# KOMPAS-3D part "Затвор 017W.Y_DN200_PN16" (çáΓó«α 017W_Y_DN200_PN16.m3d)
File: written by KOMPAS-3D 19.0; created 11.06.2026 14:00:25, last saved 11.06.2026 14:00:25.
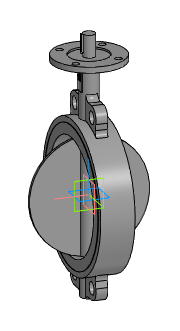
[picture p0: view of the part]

Document properties: Автор: Евгений; Полное имя файла: Z:\3.Личные\kachalov\001_3d для проектировщиков\x.x Тип 017W.Y(S) Затвор дисковый поворотный межфланцевый\_stp_Затвор 017W.Y_DN50-DN350\Затвор 017W_Y_DN200_PN16.m3d

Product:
- Part/product: Затвор 017W.Y_DN200_PN16

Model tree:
1. Операция без истории:1  (labels: Затвор 017W.Y_DN200_PN16)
